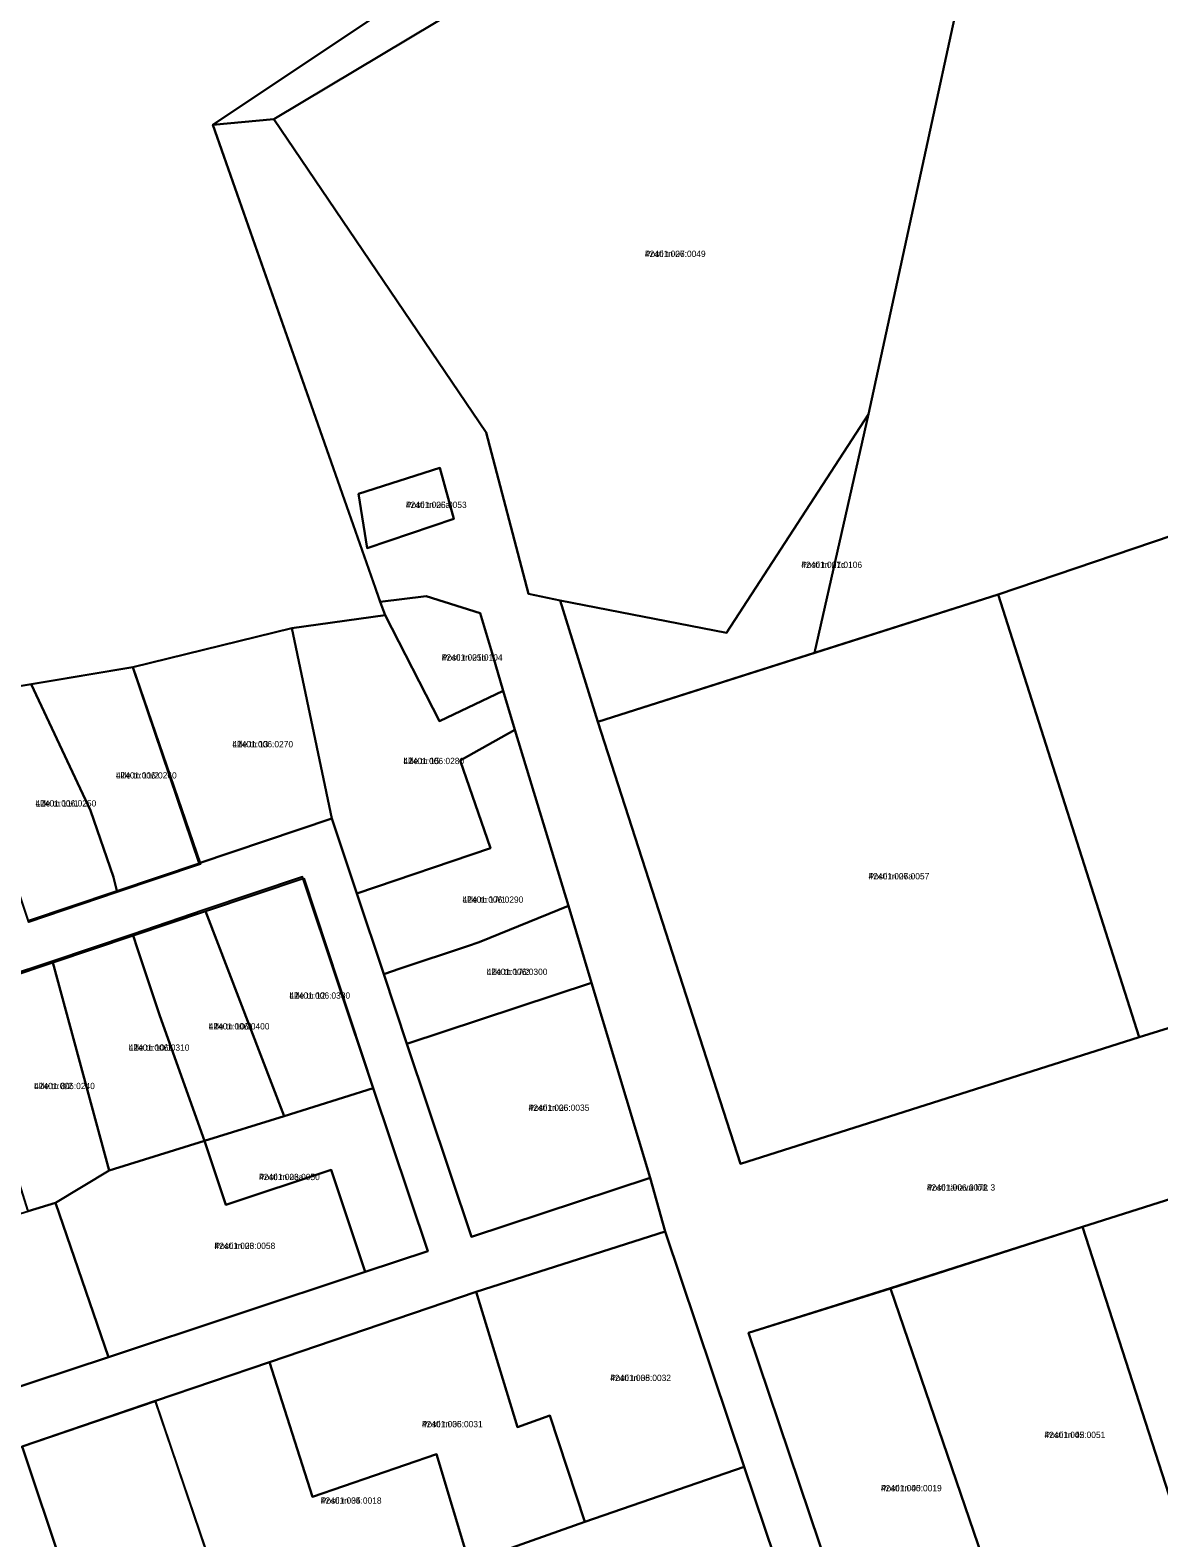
# Model space of a CAD drawing. Extents: x 595979 to 597983, y 6604231 to 6607350.
# Drawn here: x 597511.5 to 597780.8, y 6606558.1 to 6606917.7 of the extents above; entities that cross this region are included whole.
import ezdxf

# ---------------------------------------------------------------- set-up
doc = ezdxf.new("R2010")
doc.units = 0
for name, color, linetype in [('L_AADRESS', 7, 'Continuous'), ('PIIR', 7, 'Continuous'), ('TUNNUS', 7, 'Continuous')]:
    doc.layers.add(name, color=color, linetype=linetype)

msp = doc.modelspace()

# ---------------------------------------------------------------- linework, layer by layer
at = {"layer": 'PIIR'}
for points in [[(597756.25, 6607029.31), (597555.1, 6606895.13), (597595.03, 6606781.37), (597596.23, 6606778.19), (597573.92, 6606775.05), (597536, 6606765.81), (597493.26, 6606758.6), (597491.45, 6606773.47), (597488.27, 6606921.71), (597488.02, 6606934.96), (597483.37, 6607176.6), (597483.18, 6607186.71)], [(597756.25, 6607029.31), (597746.71, 6606988.38), (597685.82, 6606966), (597569.6, 6606896.5), (597555.1, 6606895.13)], [(597960.77, 6606911.42), (597931.09, 6606776.25), (597855.49, 6606801.38), (597825.72, 6606811.32), (597742.46, 6606783.1), (597698.67, 6606769.19), (597711.53, 6606826.13), (597746.71, 6606988.38), (597756.25, 6607029.31)], [(597569.6, 6606896.5), (597685.82, 6606966), (597746.71, 6606988.38), (597711.53, 6606826.13), (597677.66, 6606773.95), (597637.97, 6606781.71), (597630.36, 6606783.24), (597620.29, 6606821.78)], [(597711.53, 6606826.13), (597698.67, 6606769.19), (597646.95, 6606752.76), (597637.97, 6606781.71), (597677.66, 6606773.95)], [(597589.87, 6606807.1), (597609.23, 6606813.3), (597612.6, 6606801.16), (597591.9, 6606794.19)], [(597589.87, 6606807.1), (597591.9, 6606794.19), (597612.6, 6606801.16), (597609.23, 6606813.3)], [(597827.06, 6606693.36), (597776.08, 6606677.55), (597742.46, 6606783.1), (597825.72, 6606811.32), (597855.49, 6606801.38)], [(597624.38, 6606760.14), (597609.16, 6606752.89), (597596.23, 6606778.19), (597595.03, 6606781.37), (597606, 6606782.69), (597618.85, 6606778.66), (597621.95, 6606768.28)], [(597646.95, 6606752.76), (597742.46, 6606783.1), (597776.08, 6606677.55), (597680.99, 6606647.32)], [(597583.45, 6606729.71), (597573.92, 6606775.05), (597596.23, 6606778.19), (597609.16, 6606752.89), (597624.38, 6606760.14), (597627.15, 6606750.86), (597614.08, 6606743.54), (597621.35, 6606722.6), (597589.42, 6606711.75)], [(597573.92, 6606775.05), (597583.45, 6606729.71), (597551.84, 6606719.04), (597536, 6606765.81)], [(597531.35, 6606715.69), (597525.92, 6606731.59), (597511.76, 6606761.71), (597536, 6606765.81), (597552.16, 6606718.75), (597532.28, 6606712.08)], [(597511.76, 6606761.71), (597525.92, 6606731.59), (597531.35, 6606715.69), (597532.28, 6606712.08), (597511.17, 6606704.98), (597493.26, 6606758.6)], [(597595.86, 6606692.58), (597589.42, 6606711.75), (597621.35, 6606722.6), (597614.08, 6606743.54), (597627.15, 6606750.86), (597639.9, 6606708.84), (597618.62, 6606700.16), (597615.88, 6606699.23), (597599.79, 6606693.87)], [(597384.66, 6606650.83), (597374.77, 6606639.01), (597389.6, 6606595.35), (597402.03, 6606558.78), (597476.94, 6606583.64), (597530.15, 6606601.23), (597591.43, 6606621.52), (597606.41, 6606626.45), (597593.33, 6606665.34), (597576.47, 6606715.76), (597553.04, 6606707.89), (597535.82, 6606702.03), (597516.63, 6606695.54), (597494.23, 6606688.14), (597473.02, 6606681.13), (597453.62, 6606674.41), (597434.23, 6606667.71), (597413.88, 6606660.78), (597390.59, 6606652.82)], [(597576.8, 6606715.48), (597593.33, 6606665.34), (597572.12, 6606658.71), (597553.36, 6606707.55)], [(597601.37, 6606675.9), (597595.86, 6606692.58), (597599.79, 6606693.87), (597615.88, 6606699.23), (597618.62, 6606700.16), (597639.9, 6606708.84), (597645.46, 6606690.48)], [(597542.47, 6606682.6), (597537.13, 6606698.62), (597536.08, 6606701.75), (597553.36, 6606707.55), (597572.12, 6606658.71), (597553.12, 6606652.79)], [(597536.08, 6606701.75), (597537.13, 6606698.62), (597542.47, 6606682.6), (597553.12, 6606652.79), (597530.34, 6606645.73), (597516.88, 6606695.3)], [(597495.6, 6606684.59), (597494.52, 6606687.87), (597516.88, 6606695.3), (597530.34, 6606645.73), (597517.56, 6606638.05), (597511.06, 6606636.01), (597500.75, 6606668.57)], [(597601.37, 6606675.9), (597645.46, 6606690.48), (597659.45, 6606643.96), (597616.76, 6606629.89)], [(597553.12, 6606652.79), (597572.12, 6606658.71), (597593.33, 6606665.34), (597606.41, 6606626.45), (597591.43, 6606621.52), (597583.33, 6606645.87), (597558.19, 6606637.53)], [(597517.56, 6606638.05), (597530.34, 6606645.73), (597553.12, 6606652.79), (597558.19, 6606637.53), (597583.33, 6606645.87), (597591.43, 6606621.52), (597530.15, 6606601.23)], [(597464.23, 6606622.07), (597469.38, 6606624.1), (597480.46, 6606627.66), (597480.81, 6606638.66), (597488.73, 6606641.73), (597494.58, 6606640), (597498.4, 6606632.17), (597511.06, 6606636.01), (597517.56, 6606638.05), (597530.15, 6606601.23), (597476.94, 6606583.64)], [(597762.54, 6606632.31), (597793.92, 6606642.25), (597831.54, 6606619.92), (597871.24, 6606596.51), (597853.26, 6606565.17), (597790.29, 6606546.25)], [(597716.73, 6606617.61), (597762.54, 6606632.31), (597790.29, 6606546.25), (597746.05, 6606532.03)], [(597617.92, 6606616.81), (597662.99, 6606631.17), (597681.85, 6606575.06), (597643.81, 6606561.92), (597635.47, 6606587.26), (597627.8, 6606584.54)], [(597568.59, 6606600.02), (597617.92, 6606616.81), (597627.8, 6606584.54), (597635.47, 6606587.26), (597643.81, 6606561.92), (597616.25, 6606552.17), (597608.42, 6606578.08), (597578.83, 6606567.87)], [(597682.91, 6606606.97), (597716.73, 6606617.61), (597746.05, 6606532.03), (597711.99, 6606520.69)], [(597541.38, 6606590.75), (597568.59, 6606600.02), (597578.83, 6606567.87), (597608.42, 6606578.08), (597616.25, 6606552.17), (597575.11, 6606537.67), (597568.32, 6606535.1), (597561.14, 6606532.48)], [(597509.62, 6606579.92), (597541.36, 6606590.73), (597561.14, 6606532.48), (597529.16, 6606521.4)], [(597503.02, 6606512.14), (597481.32, 6606570.54), (597509.62, 6606579.92), (597529.16, 6606521.4)], [(597575.11, 6606537.67), (597616.25, 6606552.17), (597643.81, 6606561.92), (597681.85, 6606575.06), (597701.21, 6606517.72), (597712.18, 6606485.07), (597604.59, 6606449.84)]]:
    msp.add_lwpolyline(points, close=True, dxfattribs=at)
for points in [[(597701.21, 6606517.72), (597681.85, 6606575.06), (597662.99, 6606631.17), (597659.45, 6606643.96), (597645.46, 6606690.48), (597639.9, 6606708.84), (597627.15, 6606750.86), (597624.38, 6606760.14), (597621.95, 6606768.28), (597618.85, 6606778.66), (597606, 6606782.69), (597595.03, 6606781.37), (597593.81, 6606784.82), (597555.1, 6606895.13), (597569.6, 6606896.5), (597620.29, 6606821.78), (597630.36, 6606783.24), (597637.97, 6606781.71), (597646.95, 6606752.76), (597680.99, 6606647.32), (597776.08, 6606677.55), (597827.06, 6606693.36)], [(597510.84, 6606705.27), (597531.97, 6606712.38), (597551.84, 6606719.04), (597583.45, 6606729.71), (597589.42, 6606711.75), (597595.86, 6606692.58), (597601.37, 6606675.9), (597616.76, 6606629.89), (597659.45, 6606643.96), (597662.99, 6606631.17), (597617.92, 6606616.81), (597568.59, 6606600.02), (597541.38, 6606590.75), (597509.62, 6606579.92)], [(597793.92, 6606642.25), (597762.54, 6606632.31), (597716.76, 6606617.62), (597682.91, 6606606.97), (597711.99, 6606520.69)]]:
    msp.add_lwpolyline(points, dxfattribs=at)

# ---------------------------------------------------------------- texts
at = {"layer": 'L_AADRESS'}
for s, p in [('Posti tn 27', (597658.16, 6606863.61)), ('Posti tn 25a', (597601.14, 6606803.75)), ('Posti tn 27c', (597695.48, 6606789.45)), ('Posti tn 25b', (597609.71, 6606767.34)), ('Lille tn 13', (597559.73, 6606746.65)), ('Lille tn 15', (597600.54, 6606742.65)), ('Lille tn 11/2', (597531.96, 6606739.22)), ('Lille tn 11/1', (597512.77, 6606732.54)), ('Posti tn 27a', (597711.52, 6606715.15)), ('Lille tn 17/1', (597614.66, 6606709.58)), ('Lille tn 17/2', (597620.41, 6606692.37)), ('Lille tn 12', (597573.34, 6606686.7)), ('Lille tn 10/2', (597554.1, 6606679.36)), ('Lille tn 10/1', (597535, 6606674.28)), ('Lille tn 8/2', (597512.43, 6606665.13)), ('Posti tn 25', (597630.41, 6606659.95)), ('Posti tn 23a', (597566.1, 6606643.43)), ('Posti tänava lõik 3', (597725.45, 6606640.93)), ('Posti tn 23', (597555.47, 6606627.01)), ('Posti tn 38', (597649.89, 6606595.51)), ('Posti tn 36', (597604.96, 6606584.49)), ('Posti tn 42', (597753.51, 6606581.92)), ('Posti tn 34', (597580.84, 6606566.25)), ('Posti tn 40', (597714.48, 6606569.21))]:
    msp.add_text(s, height=1.5, dxfattribs=at).set_placement(p)
at = {"layer": 'TUNNUS'}
for s, p in [('42401:006:0049', (597658.16, 6606863.61)), ('42401:006:0053', (597601.14, 6606803.75)), ('42401:001:0106', (597695.48, 6606789.45)), ('42401:001:0104', (597609.71, 6606767.34)), ('42401:006:0270', (597559.73, 6606746.65)), ('42401:006:0280', (597600.54, 6606742.65)), ('42401:006:0260', (597531.96, 6606739.22)), ('42401:006:0250', (597512.77, 6606732.54)), ('42401:006:0057', (597711.52, 6606715.15)), ('42401:006:0290', (597614.66, 6606709.58)), ('42401:006:0300', (597620.41, 6606692.37)), ('42401:006:0380', (597573.34, 6606686.7)), ('42401:006:0400', (597554.1, 6606679.36)), ('42401:006:0310', (597535, 6606674.28)), ('42401:006:0240', (597512.43, 6606665.13)), ('42401:006:0035', (597630.41, 6606659.95)), ('42401:006:0050', (597566.1, 6606643.43)), ('42401:006:0072', (597725.45, 6606640.93)), ('42401:006:0058', (597555.47, 6606627.01)), ('42401:005:0032', (597649.89, 6606595.51)), ('42401:005:0031', (597604.96, 6606584.49)), ('42401:005:0051', (597753.51, 6606581.92)), ('42401:005:0018', (597580.84, 6606566.25)), ('42401:005:0019', (597714.48, 6606569.21))]:
    msp.add_text(s, height=1.5, dxfattribs=at).set_placement(p)

doc.saveas('drawing.dxf')
